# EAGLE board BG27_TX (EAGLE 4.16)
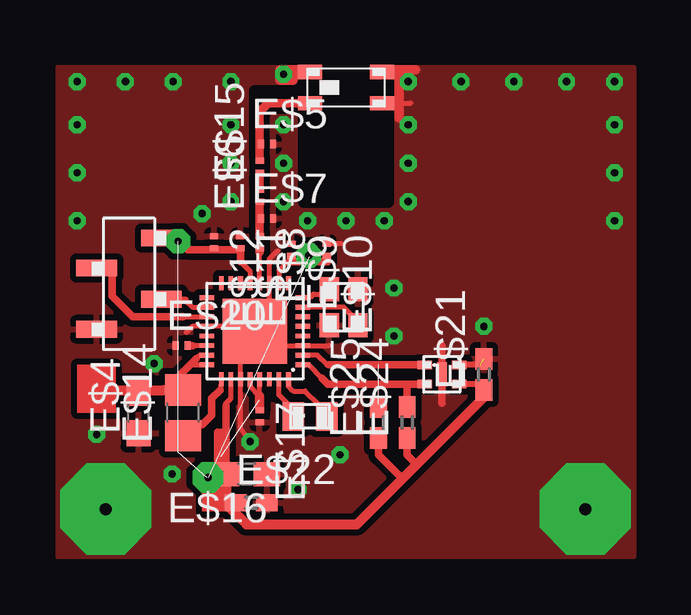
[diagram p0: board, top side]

No outline drawn. Coordinates in mm, seen from the top.
Copper layers (1*16): Top 0.035mm / dielectric 1.5mm / Bottom 0.035mm
Design rules "default": minimum track width 10mil, minimum drill 24mil, track to track 8mil, track to pad 8mil, pad to pad 8mil, via to via 8mil, smd to smd 8mil, copper to edge 40mil, drill to drill 8mil, minimum pad ring 10mil, minimum via ring 8mil, stop-mask expansion 4mil, vias tented up to drill 0mil, thermal gap 10mil
tRestrict: area 10.2,14.8 to 13.8,20.5; area 8.2,18.8 to 10.2,19.4; area 7.5,2.6 to 8.2,3.9

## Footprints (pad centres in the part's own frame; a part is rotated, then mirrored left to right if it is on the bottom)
ANT_2.4 = smd 1 x 0.6: P$1 -1.5,0.65; P$2 -1.5,-0.65; P$3 1.5,-0.65; P$4 1.5,0.65
QFN32_04 = smd 0.6 x 0.2: 1 -2,1.4; 2 -2,1; 3 -2,0.6; 4 -2,0.2; 5 -2,-0.2; 6 -2,-0.6; 7 -2,-1; 8 -2,-1.4; 17 2,-1.4; 18 2,-1; 19 2,-0.6; 20 2,-0.2; 21 2,0.2; 22 2,0.6; 23 2,1; 24 2,1.4 | smd 0.2 x 0.6: 9 -1.4,-2; 10 -1,-2; 11 -0.6,-2; 12 -0.2,-2; 13 0.2,-2; 14 0.6,-2; 15 1,-2; 16 1.4,-2; 25 1.4,2; 26 1,2; 27 0.6,2; 28 0.2,2; 29 -0.2,2; 30 -0.6,2; 31 -1,2; 32 -1.4,2 | smd 2.7 x 2.7: EP 0,0
SH4X = smd 0.6 x 0.35: 1 -0.725,0.4; 2 -0.725,-0.4; 3 0.725,-0.4; 4 0.725,0.4 | smd 0.4 x 1: EP 0,0
C0603 = smd 1.1 x 1: 1 -0.85,0; 2 0.85,0
C0201 = smd 0.25 x 0.35: 1 -0.25,0; 2 0.25,0
HEADERS4 = smd 0.7 x 1.7: P$1 1.27,1.35; P$3 -1.28,1.35; P$4 -0.03,-1.35; P$5 2.52,-1.35
C0805 = smd 1.3 x 1.5: 1 -0.95,0; 2 0.95,0
38.4 = smd 1 x 0.8: P$1 -0.75,0.6; P$2 -0.75,-0.6; P$3 0.75,-0.6; P$4 0.75,0.6
ECS_2216 = smd 0.9 x 1.2: P$1 -0.7,0; P$2 0.7,0
C0402 = smd 0.9 x 0.7: 1 -0.65,0; 2 0.65,0

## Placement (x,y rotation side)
E$1  [ANT_2.4]  12,19.55 0 top
E$2  [QFN32_04]  8.2,9.4 180 top
E$3  [SH4X]  16,7.6 0 top
E$4  [C0603]  3.35,6 90 top
E$5  [C0201]  8.7,17.2 0 top
E$6  [C0201]  8.4,15.05 90 top
E$7  [C0201]  8.7,14.1 0 top
E$8  [C0201]  8.4,13.1 270 top
E$9  [C0201]  9.72,12.8 270 top
E$10  [C0201]  11.2,12.8 270 top
E$11  [C0201]  7.6,13.1 270 top
E$12  [C0201]  6.5,13.1 270 top
E$13  [HEADERS4]  2.95,12 270 top
E$14  [C0805]  5.2,6 90 top
E$15  [C0201]  8.4,16.25 90 top
E$16  [C0603]  7.85,3.45 180 top
E$17  [C0201]  8.4,5.85 270 top
E$18  [38.4]  11.9,10.4 90 top
E$19  [ECS_2216]  10.5,5.85 180 top
E$20  [C0201]  5.15,8.8 0 top
E$21  [C0402]  17.75,7.6 90 top
E$22  [C0402]  8.05,2.25 0 top
E$24  [C0402]  14.55,5.6 90 top
E$25  [C0402]  13.35,5.6 90 top

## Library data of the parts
E$1 = johanson
E$2 = silabs
E$3 = sensor
E$4-E$12 E$14-E$17 E$20-E$22 E$24 E$25 = ref-packages
E$13 = sb
E$18 E$19 = crystal

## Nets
GND: E$1.P$1 E$1.P$3 E$1.P$4 E$4.1 E$5.2 E$7.2 E$9.1 E$10.1 E$11.1 E$12.1 E$13.P$5 E$16.1 E$17.2 E$18.P$1 E$18.P$3 E$20.1 E$21.2 E$22.2

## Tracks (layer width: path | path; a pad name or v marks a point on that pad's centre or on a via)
GND  (via drill 0.3 pad 0.61, 0.5 pad 3.81)  (3 unrouted)
  Top 0.2: 9.2,8.8 11.3,8.8 | v8,4.8 7.6,5.35 7.6,9.6 5.6,9.6 5.35,9.35 | 8.8,10.4 8.8,12.4 9.15,12.75 | 11.36,13.06 11.81,13.06 | E$1.P$3 14.7,18.9
  Top 0.254: 17.6,8 16.8,8
  Top 0.305: 16,6.4 16,8.8 | 9.54,20.34 10.54,20.34
  Top 0.4: 9.25,20.3 9.8,20.3 9.8,19.86 9.25,19.86 | 14.2,20.3 14.2,18.3 | 14.2,20.3 14.9,20.3 | 13.5,20.3 14.2,20.3
  other vias: 1.98,1.99 4.75,3.45 4,8.05 10,2.8 0.8,14 0.8,16 21.98,1.99 0.8,18 6,14.3 7.2,14.8 0.8,19.8 14,9.2 4.8,19.8 9.4,14.8 2.8,19.8 7.2,16.4 11.75,4.25 14,11.2 7.2,19.8 9.4,16.4 10.4,14 12,14 7.2,18 9.4,18 9.4,20.1 13.6,14 14.6,14.8 14.6,16.4 14.6,18 14.6,19.8 23.2,14 16.8,19.8 23.2,16 19,19.8 23.2,18 23.2,19.8 1.6,5.1 17.75,9.6 21.2,19.8
  pour Top (isolate 0.26): 0,0 0,20.4 24,20.4 24,0
S$1
  Top 0.35: 10.15,18.9 8.75,18.9 8.4,18.55 8.4,16.6
S$2
  Top 0.35: 8.4,15.45 8.4,15.85
S$3
  Top 0.254: 17.6,7.2 16.8,7.2
S$4
  Top 0.35: 8.4,13.5 8.4,14.65
S$5
  Top 0.2: 8.4,11.6 8.4,12.75
  Top 0.35: 8.4,12.75 8.4,12.7
S$6
  Top 0.2: 9.2,11.6 9.2,11.95 9.55,12.3 9.65,12.3
  Top 0.305: 9.65,12.3 11.22,12.3
S$7
  Top 0.305: 13.35,4.65 13.35,4.25 14.35,3.25
S$8  (via drill 0.3 pad 1.02)
  other vias: 10.45,12.55
S$9
  Top 0.406: 6.7,2.15 7.05,2.15 7.85,1.35 12.45,1.35 17.75,6.65
S$10
  Top 0.2: 8,11.6 8,11.9 7.6,12.3
  Top 0.305: 7.6,12.3 7.6,12.8 5.4,12.8 5.05,13.15
S$11
  Top 0.305: 14.55,4.65 14.55,4.25 14.9,3.9
S$12  (via drill 0.3 pad 1.02)
  other vias: 5,13.15
S$13
  Top 0.2: 5.5,8 6,8
S$14
  Top 0.2: 10.4,8 10.45,8 11,7.45
  Top 0.305: 11,7.45 11.25,7.2 14.55,7.2 | 14.55,7.2 15.05,7.2 | 14.55,7.2 14.55,6.4
S$15
  Top 0.305: 6.8,3.6 6.8,5.2
S$16
  Top 0.2: 5.3,10.7 5.6,10.4 6,10.4
  Top 0.305: 4.15,10.7 5.3,10.7
S$17
  Top 0.2: 5.2,10 6,10
  Top 0.305: 2.25,11.95 2.25,10.85 3.1,10 5.2,10
S$18
  Top 0.305: 6.65,3.6 6.65,5.2
S$19
  Top 0.2: 6.8,7.2 6.8,7 6.75,6.95
  Top 0.305: 5.3,5.5 6,5.5 6.4,5.9 6.4,6.6 6.75,6.95
S$21
  Top 0.2: 7,6.3 7,6.4 7.2,6.6 7.2,7.2
  Top 0.305: 7,2.35 7,6.3
S$22
  Top 0.2: 8.4,6.15 8.4,7.2
S$23
  Top 0.2: 8.4,6.7 8,7.1 8,7.2
  Top 0.4: 8.4,6.7 8.4,6.2
S$25
  Top 0.2: 10.4,10.8 10.5,10.8 10.65,10.95 11.5,10.95
S$26
  Top 0.2: 10.4,10.4 11.9,10.4 12.6,9.7
S$27
  Top 0.2: 9.6,7.6 9.6,7.1 9.8,6.9 10.3,6.9 10.85,6.35
S$28
  Top 0.2: 9.2,7.2 9.2,6.75 10,5.95
S$30
  Top 0.2: 11.3,8 11.2,8 10.8,8.4 10.4,8.4
  Top 0.305: 11.3,8 15.35,8
S$32  (via drill 0.3 pad 1.27)
  other vias: 6.25,3.3
S$33
  Top 0.2: 6,8.8 5.6,8.8
  Top 0.305: 5.6,8.8 5.45,8.8
S$41
  Top 0.305: 11.22,12.3 11.22,12.5
S$60
  Top 0.2: 5.75,8.25 5.9,8.4 6,8.4
  Top 0.305: 4.4,6.95 4.45,6.95 5.75,8.25
  Top 0.406: 1.6,6.95 4.4,6.95
(copper drawn outside any net)
  shapes: Top area x2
